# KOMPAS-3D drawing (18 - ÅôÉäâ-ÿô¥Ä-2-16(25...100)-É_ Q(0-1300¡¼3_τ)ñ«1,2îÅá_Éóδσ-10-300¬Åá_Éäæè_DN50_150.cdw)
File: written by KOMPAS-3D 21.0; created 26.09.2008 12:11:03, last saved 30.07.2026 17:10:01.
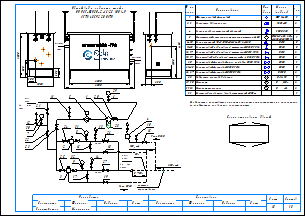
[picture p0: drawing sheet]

Sheets 1-2: A3, landscape

Document properties: Наименование: Макро:21; Автор: RaskoAdmin; Форматы листов документа: 2xA3; Полное имя файла: \\ur38nt01\Departments\КТО\КБ ПУРДГ\Заявки\Прайс-лист на типовые шкафы ГРПШ\ПУРДГ_стандарт_30_04_2026\ПУРДГ с РДСК\ПУРДГ-ШУЭО-2-16(25...100)-Р_ Q(0-1300нм3_ч)до1,2МПа_Рвых-10-300кПа_РДСК_DN50_150.cdw

Title block, sheet 1: Наименование: Пункт учета газа / ПУГ-Ш-400-Р / ЛГТИ.485922.001ТУ; designation: ЛГТИ.03.4411141; sheet number: 1; Количество листов документа: 2; organisation: ООО "ЭЛЬСТЕР Газэлектроника"; Форматы листов документа: A3; stored path: C:\Рабочие документы\Компас\ПУГ\Схема.cdw; Разработал: Устинов; Проверил: Кошкин; Утвердил: Кошкин
Title block, sheet 2: sheet number: 2; stored path: D:\Рабочие документы\Заявки\ПУРДГ\ПУРДГ-ШУЭО-2-100-Р 4411220.cdw; designation, second copy: ЛГТИ.03.4411141-

Views: Вид 1, Вид 2
Referenced files: wcvoit.frw
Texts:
  Normal
  DN150
  Выход газа
  DN50
  Вход газа
  logo-rasko-ge.png
  DN 1
  местное
  сопротивление
  Римп DN20
  Выход
  газа
  Р=     кПа
  Вход
  Р=       МПа
  PDI
  Общий вид и габариты шкафа
  ПУРДГ-ШУЭО-2-16(25...100)-Р
  № на
  схеме
  Усл.
  обозн.
  Марка
  (модель)
  Кол.
  Фильтр газовый фланцевый
  ФГ 16-50
  Регулятор давления газа
  РДСК-50
  Клапан предохранительный сбросной
  КПС DN20
  Измерительный комплекс с ротационным счетчиком Ду50
  СГ-ЭК-Р-(0,2...2,0)-
  Кран кнопочный VE-РАСКО-НЗ-1,6-G1/2-М20
  DN15
  Кран шаровой "под приварку" штуцерный DN20 PN16
  DN20
  Кран шаровой "под приварку" штуцерный DN15 PN16
  Кран шаровой "под приварку" штуцерный п/п DN20 PN16
  Кран шаровой фланцевый с мех. приводом DN50 PN16
  Кран шаровой фланцевый DN50 PN16
  Кран шаровой фланцевый DN150 PN16
  Индикатор перепада давления
  Манометр
  Манометр-напоромер
  Электрообогреватель взрывозащищенный 400Вт
  Delta 15
  0...     МПа
  0...     кПа
  Схема открывания дверей
  Предприятие изготовитель может заменять комплектующие на аналогичные,
  не ухудшающие заявленных характеристик.
  Должность
  Конструктор
  Фамилия
  Подпись
  Дата
  Согласовано
  Максимкин
  Лист
  Листов
  POLYLINE_STYLE_0.18_RGB_0_0_0
  POLYLINE_STYLE_0.50_RGB_0_0_0
  POLYLINE_STYLE_0.34_RGB_0_0_0
  PHANTOM_RGB_0_0_0_SC_1_THICK_0.18
  K5LT_THIN_RGB_0_0_0_THICK_0.18
  K5LT32769_RGB_0_0_0_THICK_0.18
  K5LT12_RGB_0_0_0_SC_1_THICK_0.18
  K5LT_DASHED_RGB_0_0_0_SC_1_THICK_0.18
  ACISOTGL_RGB_0_0_0_SC_0.8_THICK_0.25
  CONTINUOUS_RGB_0_127_31_THICK_0.3
  CONTINUOUS_RGB_0_0_255_THICK_0.35
  CONTINUOUS_RGB_255_0_0_THICK_0.35
  POLYLINE_STYLE_0.25_RGB_0_0_0
  CONTINUOUS_RGB_0_0_0_THICK_0.5
  POLYLINE_STYLE_0.35_RGB_0_0_255
  CONTINUOUS_RGB_0_0_0_THICK_0.4
  CONTINUOUS_RGB_0_0_0_THICK_0.35
  НЕВИДИМАЯ_RGB_0_0_0_SC_0.3_THICK_0.25
  СONTINUOUS_RGB_0_0_0_THICK_0.25
  ОСЕВАЯ2_RGB_248_153_30_SC_0.3_THICK_0.25
  Без оформления
Dimensions and other numbers on the sheet: 1; 1500; 250; 300; 1050; 550; 305; 2500; 4130; 2000; 2800; 5,,,7DN 1; 7; 30; 12; 21; 22; 23; 11; 5; 20; 6; 29; 24; 31; 8; 2; 16; 13; 26; 18; 4; 10; 15; 25; 32; 9; 3; 17; 14; 27; 19; 28; 2, 3; 6-10; 11-15; 16, 17; 18, 19; 21-25; 26, 27; 29, 30; 31, 32; 33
